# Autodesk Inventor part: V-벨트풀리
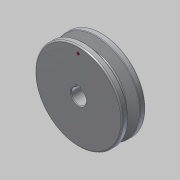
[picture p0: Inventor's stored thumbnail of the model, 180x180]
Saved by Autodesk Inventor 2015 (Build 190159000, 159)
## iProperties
Created: 2016-08
Part Number: V-벨트풀리
Material: 알루미늄 6061
Document SubType Name: Modeling
Designer: mduedu
Density: 2.71 g/cm^3
Appearance: 알루미늄 - 평지
Author: mduedu
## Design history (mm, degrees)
sketch "스케치1"
  geometry: L1 (0, 9.5)-(0, -9.5); L2 (0, 9.5)-(35, 9.5); L3 (35, 9.5)-(35, 4.825); L4 (35, 4.825)-(26, 2.074); L5 (26, 2.074)-(26, 0); L6 (0, 0)-(26, 0); L7 (0, -9.5)-(35, -9.5); L8 (35, -9.5)-(35, -4.825); L9 (35, -4.825)-(26, -2.074); L10 (26, -2.074)-(26, 0); L11 (32.3, 9.5)-(32.3, -9.5); 3 further points
  constraints: 22 end point, 6 point on line, 4 perpendicular, 3 symmetric about line, 1 coincident, 1 horizontal alignment, 1 midpoint, 1 parallel, 1 vertical
  dimensions: "d0" = 19 distance of L1.start L1.end; "d2" = 70 diameter of L8 L1; "d4" = 6.3 distance between parallel lines of L10 L11; "d5" = 2.7 distance between parallel lines of L11 L8; "d6" = 8 distance of point (32.3, -4) point (32.3, 4); "d7" = 34 deg angle of L9 L4
revolve "회전1" sketch "스케치1" stored, may be unused: angle "d8" = 90 deg
sketch "스케치2"
  geometry: L1 (-2, 0)-(2, 0); L2 (2, 0)-(2, 7.8); L3 (2, 7.8)-(-2, 7.8); L4 (-2, 7.8)-(-2, 0); C1 r 6 at (0, 0); 2 further points
  constraints: 8 end point, 2 coincident, 2 parallel, 1 centre point, 1 horizontal, 1 midpoint, 1 perpendicular
  dimensions: "d9" = 12 diameter of C1; "d11" = 4 distance of L2.end L3.end; "d12" = 7.8 distance of L1.end L2.end
extrude "돌출1" cut sketch "스케치2" stored distance "d13" = 10; taper "d14" = 0 deg
sketch "스케치4"
  geometry: C1 r 22 at (0, 0); C2 r 12 at (0, 0); 1 further point
  constraints: 2 centre point, 2 coincident
  dimensions: "d32" = 44 diameter of C1; "d34" = 24 diameter of C2
extrude "돌출2" cut sketch "스케치4" distance "d35" = 12; taper "d36" = 0 deg
fillet "모깎기1" dims "d20" = 0.5, "d21" = 1, "d37" = 1
fillet "모깎기6" dims "d38" = 3
chamfer "모따기1" distance "d26" = 0.5; stored, may be unused: second distance "d27" = 2, angle "d28" = 45 deg
sketch "스케치5" dims "d39" = 60
  geometry: C1 r 1 at (0, 30); 2 further points
  constraints: 2 vertical alignment, 1 centre point, 1 coincident, 2 other
  dimensions: "d40" = 2 diameter of C1
extrude "돌출3" join sketch "스케치5" distance "d41" = 0.5; taper "d42" = 0 deg
node "솔리드1"
